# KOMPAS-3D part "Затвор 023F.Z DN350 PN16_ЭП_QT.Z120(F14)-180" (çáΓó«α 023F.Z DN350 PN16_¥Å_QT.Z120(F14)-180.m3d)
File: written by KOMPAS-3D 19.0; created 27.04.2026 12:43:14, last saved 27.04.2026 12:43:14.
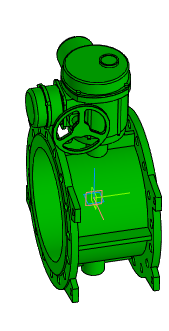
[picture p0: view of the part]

Document properties: Полное имя файла: Затвор 023F.Z DN350 PN16 + электропривод QT.Z120(F14)-180.a3d

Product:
- Part/product: Затвор 023F.Z DN350 PN16_ЭП_QT.Z120(F14)-180
    Масса: 201.393
  - Body: Тело 1
      Масса: 201.908

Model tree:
1. Операция без истории:1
